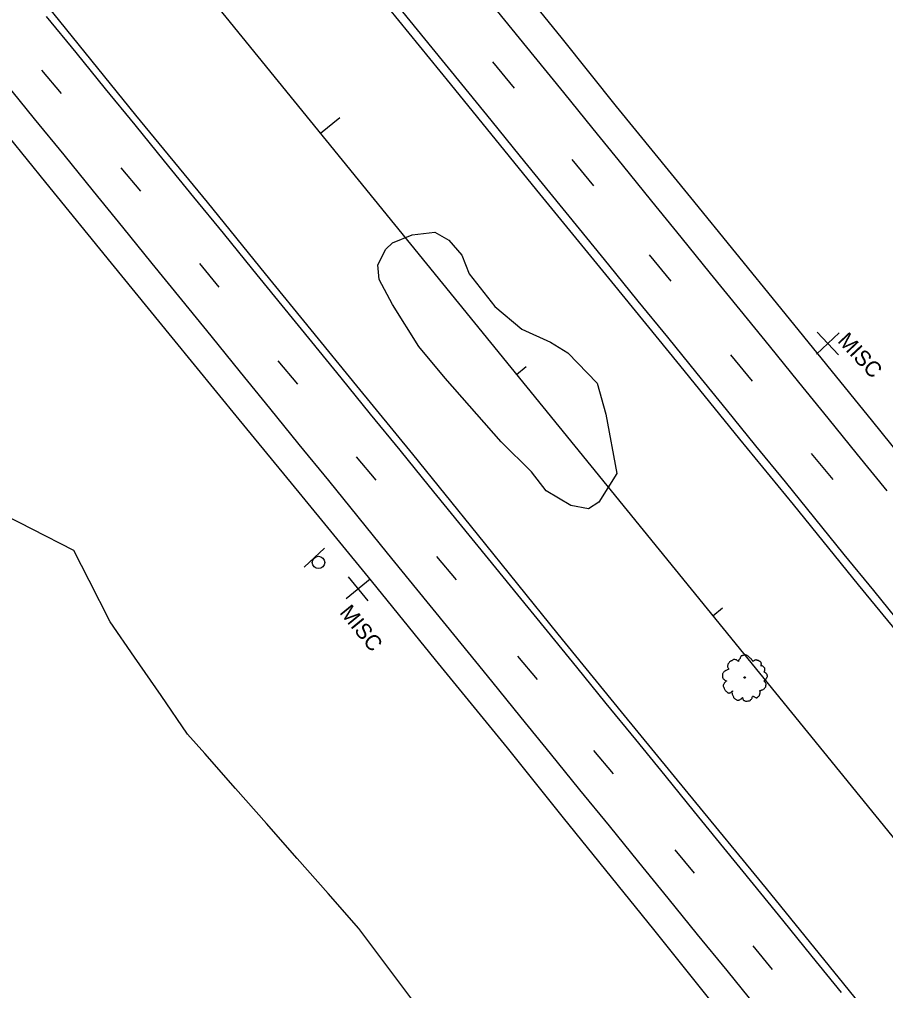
# Model space of a CAD drawing. Extents: x 2132221 to 2141942, y 535736 to 547298.
# Drawn here: x 2137299.4 to 2137577.9, y 541243.7 to 541556.1 of the extents above; entities that cross this region are included whole.
import ezdxf

# ---------------------------------------------------------------- set-up
doc = ezdxf.new("R2010")
doc.units = 0
for name, color, linetype in [('RD_EX_BldgApp', 7, 'Continuous'), ('RD_EX_Misc', 7, 'Continuous'), ('RD_EX_Misc_txCode', 7, 'Continuous'), ('RD_EX_Road', 7, 'Continuous'), ('RD_EX_VEG', 7, 'Continuous'), ('RD_HC_Cl', 7, 'Continuous'), ('RD_HC_Data_Tic', 7, 'Continuous')]:
    doc.layers.add(name, color=color, linetype=linetype)

msp = doc.modelspace()

# ---------------------------------------------------------------- linework, layer by layer
at = {"layer": 'RD_EX_BldgApp'}
msp.add_line((2137397.51, 541385.93), (2137390.9, 541379.82), dxfattribs=at)
msp.add_circle((2137395.56, 541381.38), 2, dxfattribs=at)
at = {"layer": 'RD_EX_Misc'}
for p, q in [((2137451.48, 541542.38), (2137458.5, 541533.93)), ((2137306.47, 541539.77), (2137312.77, 541532.25)), ((2137477.02, 541510.96), (2137484.04, 541502.51)), ((2137332.02, 541508.36), (2137338.32, 541500.83)), ((2137501.88, 541480.29), (2137508.9, 541471.85)), ((2137357.23, 541477.51), (2137363.52, 541469.98)), ((2137555.71, 541448.41), (2137563.01, 541455.25)), ((2137555.94, 541455.47), (2137562.78, 541448.18)), ((2137528.02, 541448.14), (2137535.04, 541439.69)), ((2137382.5, 541446.22), (2137388.79, 541438.69)), ((2137407.71, 541415.37), (2137414, 541407.85)), ((2137553.96, 541416.47), (2137560.98, 541408.02)), ((2137433.54, 541383.33), (2137439.83, 541375.8)), ((2137404.43, 541369.74), (2137412.17, 541376.07)), ((2137405.14, 541376.78), (2137411.46, 541369.03)), ((2137459.53, 541351.27), (2137465.83, 541343.74)), ((2137484.03, 541320.91), (2137490.32, 541313.38)), ((2137510.11, 541288.98), (2137516.4, 541281.46)), ((2137535.21, 541258.02), (2137541.51, 541250.49))]:
    msp.add_line(p, q, dxfattribs=at)
for points in [[(2137445.93, 541567.48), (2137455.38, 541555.83), (2137464.84, 541544.19), (2137474.3, 541532.54), (2137483.75, 541520.9), (2137493.21, 541509.25), (2137502.66, 541497.61), (2137512.12, 541485.97), (2137521.57, 541474.32), (2137531.03, 541462.68), (2137540.48, 541451.03), (2137549.94, 541439.39), (2137559.39, 541427.74), (2137568.85, 541416.1), (2137578.31, 541404.45)], [(2137422.57, 541558.54), (2137432.03, 541546.9), (2137441.5, 541535.26), (2137450.96, 541523.63), (2137460.43, 541511.99), (2137469.89, 541500.35), (2137479.36, 541488.72), (2137488.82, 541477.08), (2137498.29, 541465.44), (2137507.75, 541453.8), (2137517.21, 541442.17), (2137526.68, 541430.53), (2137536.14, 541418.89), (2137545.61, 541407.26), (2137555.07, 541395.62), (2137564.54, 541383.98), (2137574, 541372.35), (2137583.47, 541360.71)], [(2137308.01, 541557.03), (2137317.48, 541545.4), (2137326.95, 541533.77), (2137336.43, 541522.14), (2137345.9, 541510.51), (2137355.37, 541498.88), (2137364.85, 541487.25), (2137374.32, 541475.62), (2137383.79, 541463.99), (2137393.27, 541452.36), (2137402.74, 541440.73), (2137412.21, 541429.1), (2137421.69, 541417.47), (2137431.16, 541405.84), (2137440.63, 541394.21), (2137450.11, 541382.58), (2137459.58, 541370.95), (2137469.05, 541359.32), (2137478.53, 541347.69), (2137488, 541336.06), (2137497.47, 541324.43), (2137506.91, 541312.84), (2137516.37, 541301.2), (2137525.84, 541289.56), (2137535.3, 541277.93), (2137544.77, 541266.29), (2137554.23, 541254.65), (2137563.7, 541243.01)], [(2137294.69, 541535.76), (2137304.15, 541524.12), (2137313.6, 541512.47), (2137323.06, 541500.83), (2137332.52, 541489.19), (2137341.98, 541477.55), (2137351.44, 541465.91), (2137360.9, 541454.26), (2137370.36, 541442.62), (2137379.82, 541430.98), (2137389.27, 541419.34), (2137398.73, 541407.7), (2137408.19, 541396.05), (2137417.65, 541384.41), (2137427.11, 541372.77), (2137436.57, 541361.13), (2137446.03, 541349.49), (2137451.14, 541343.19), (2137460.61, 541331.55), (2137470.07, 541319.91), (2137479.54, 541308.28), (2137489, 541296.64), (2137498.46, 541285), (2137507.93, 541273.36), (2137517.39, 541261.73), (2137526.86, 541250.09), (2137536.32, 541238.45)]]:
    msp.add_lwpolyline(points, dxfattribs=at)
at = {"layer": 'RD_EX_Road'}
for points in [[(2137193.35, 541837.19), (2137212.91, 541812.44), (2137235.27, 541784.87), (2137254.4, 541760.88), (2137274.02, 541736.87), (2137295.29, 541710.97), (2137313.63, 541688.15), (2137334.61, 541662.71), (2137358.33, 541633.36), (2137376.02, 541611.54), (2137393.61, 541589.72), (2137411.3, 541568), (2137437.87, 541535.36), (2137465.67, 541501.18), (2137489.75, 541471.68), (2137511.61, 541444.85), (2137530.92, 541421.07), (2137548.19, 541400.06), (2137569.12, 541374.18), (2137589.5, 541349.39), (2137612.36, 541321.32), (2137632.5, 541296.04), (2137648.27, 541276.75), (2137665.39, 541255.65)], [(2137129.75, 541780.57), (2137152.42, 541752.13), (2137176.05, 541723.37), (2137199.18, 541694.95), (2137221.19, 541667.61), (2137243.48, 541640.3), (2137267.28, 541610.96), (2137291.46, 541581.15), (2137312.24, 541555.53), (2137336.72, 541525.3), (2137359.73, 541497.32), (2137378.4, 541474.19), (2137407.74, 541438.19), (2137425.75, 541416.17), (2137446.57, 541390.46), (2137472.54, 541358.27), (2137492.89, 541333.37), (2137514.29, 541307.17), (2137539.52, 541276.53), (2137564.39, 541245.78), (2137586.4, 541218.72), (2137608.31, 541191.93)], [(2137100.38, 541758.24), (2137116.65, 541738.05), (2137136.57, 541713.17), (2137158.12, 541686.61), (2137181.43, 541658.3), (2137199.12, 541636.62), (2137219.56, 541611.48), (2137227.67, 541601.79), (2137247.01, 541578.63), (2137263.16, 541558.53), (2137284.05, 541532.79), (2137307.73, 541503.58), (2137328.85, 541477.64), (2137348.35, 541453.76), (2137369.96, 541427.39), (2137389.21, 541403.83), (2137412.54, 541375.44), (2137433.11, 541350), (2137456.28, 541321.75), (2137474.25, 541299.22), (2137503.28, 541263.26), (2137525.6, 541235.47)], [(2137457.68, 541569.82), (2137473.88, 541549.77), (2137491.32, 541528.01), (2137515.2, 541498.79), (2137544.12, 541463.2), (2137573.71, 541426.73), (2137595.07, 541400.23), (2137611.36, 541380.03), (2137614.73, 541374.83), (2137617.63, 541368.59), (2137619.19, 541368), (2137623.18, 541367.48), (2137626.31, 541363.68), (2137627.71, 541361.27), (2137643.36, 541341.41), (2137658.35, 541323.01), (2137679.14, 541297.23), (2137696.06, 541276.5)]]:
    msp.add_lwpolyline(points, dxfattribs=at)
at = {"layer": 'RD_EX_VEG'}
msp.add_lwpolyline([(2137454.29, 541420.16), (2137436.27, 541440.67), (2137427.84, 541450.8), (2137419.36, 541464.4), (2137415.07, 541472.45), (2137414.68, 541477.07), (2137417.19, 541482.16), (2137419.38, 541484.19), (2137425.73, 541486.72), (2137432.97, 541487.67), (2137437.47, 541485), (2137441.7, 541480.22), (2137443.96, 541474.17), (2137452.28, 541463.75), (2137460.92, 541456.39), (2137470.14, 541452.2), (2137475.7, 541448.78), (2137485.21, 541439.08), (2137487.97, 541429.08), (2137491.53, 541410.01), (2137485.68, 541400.74), (2137482.43, 541398.66), (2137476.71, 541399.65), (2137468.77, 541404.45), (2137464.11, 541410.49)], close=True, dxfattribs=at)
msp.add_lwpolyline([(2137428.45, 541237.07), (2137419.45, 541249.07), (2137410.45, 541261.08), (2137408.55, 541263.61), (2137398.64, 541274.86), (2137388.72, 541286.12), (2137378.81, 541297.38), (2137368.89, 541308.63), (2137358.98, 541319.89), (2137353.42, 541326.19), (2137344.92, 541338.55), (2137336.41, 541350.9), (2137328.58, 541362.27), (2137321.75, 541375.62), (2137316.83, 541385.25), (2137303.46, 541392.04), (2137299.47, 541394.07), (2137293.84, 541396.93)], dxfattribs=at)
for centre, radius in [((2137532.59, 541344.38), 0.25), ((2137532.57, 541344.38), 0.0001)]:
    msp.add_circle(centre, radius, dxfattribs=at)
for points in [[(2137537.95, 541349.15), (2137537.76, 541349.38), (2137537.47, 541349.56), (2137537.23, 541349.67), (2137537.02, 541349.79), (2137536.79, 541349.88), (2137536.46, 541349.98), (2137536.16, 541350.01), (2137535.89, 541349.94), (2137535.69, 541349.82), (2137535.46, 541349.67), (2137535.33, 541349.55), (2137535.23, 541349.63), (2137535.14, 541349.75), (2137535.03, 541349.99), (2137534.86, 541350.17), (2137534.69, 541350.36), (2137534.43, 541350.6), (2137534.2, 541350.85), (2137533.97, 541351.02), (2137533.72, 541351.23), (2137533.37, 541351.42), (2137533.04, 541351.59), (2137532.65, 541351.64), (2137532.14, 541351.5), (2137531.79, 541351.36), (2137531.51, 541351.3), (2137531.28, 541350.88), (2137531.14, 541350.52), (2137531.01, 541350.36), (2137530.75, 541350.02), (2137530.65, 541349.79), (2137530.59, 541349.57), (2137530.52, 541349.6), (2137530.23, 541349.85), (2137529.95, 541350), (2137529.5, 541350.16), (2137529.18, 541350.17), (2137528.88, 541350.02), (2137528.6, 541349.8), (2137528.39, 541349.74), (2137528.13, 541349.61), (2137528.06, 541349.58), (2137527.79, 541349.4), (2137527.53, 541349.02), (2137527.29, 541348.76), (2137527.21, 541348.52), (2137527.18, 541348.29), (2137527.11, 541347.99), (2137527.22, 541347.54), (2137527.37, 541347.24), (2137527.48, 541347.07), (2137527, 541346.86), (2137526.71, 541346.66), (2137526.33, 541346.48), (2137526.27, 541346.43), (2137525.89, 541346.15), (2137525.75, 541345.82), (2137525.53, 541345.51), (2137525.48, 541345.23), (2137525.45, 541344.82), (2137525.5, 541344.43), (2137525.75, 541343.98), (2137526.04, 541343.7), (2137526.56, 541343.4), (2137526.78, 541343.26), (2137526.64, 541343.16), (2137526.38, 541342.89), (2137526.07, 541342.6), (2137525.93, 541342.27), (2137525.79, 541342.01), (2137525.71, 541341.73), (2137525.77, 541341.34), (2137525.98, 541341), (2137526.16, 541340.58), (2137526.41, 541340.2), (2137526.73, 541339.82), (2137527.25, 541339.48), (2137527.53, 541339.36), (2137527.72, 541339.41), (2137528.14, 541339.51), (2137528.27, 541339.7), (2137528.72, 541340.09), (2137528.66, 541339.9), (2137528.52, 541339.53), (2137528.64, 541338.96), (2137528.79, 541338.55), (2137529, 541338.1), (2137529.15, 541337.83), (2137529.52, 541337.53), (2137529.83, 541337.31), (2137530.18, 541337.12), (2137530.58, 541337.08), (2137530.9, 541337.14), (2137531.14, 541337.29), (2137531.47, 541337.49), (2137531.63, 541337.57)], [(2137531.63, 541337.57), (2137531.71, 541337.74), (2137531.86, 541337.95), (2137531.89, 541337.88), (2137531.97, 541337.72), (2137532.07, 541337.43), (2137532.16, 541337.21), (2137532.4, 541336.99), (2137532.66, 541336.86), (2137533.17, 541336.71), (2137533.7, 541336.83), (2137534.18, 541336.9), (2137534.47, 541337.07), (2137534.61, 541337.26), (2137534.96, 541337.61), (2137535, 541337.93), (2137535.06, 541338.05), (2137535.29, 541338.4), (2137535.38, 541338.37), (2137535.6, 541338.21), (2137535.94, 541338.02), (2137536.22, 541337.9), (2137536.5, 541337.85), (2137536.72, 541337.95), (2137537, 541338.24), (2137537.32, 541338.47), (2137537.38, 541338.63), (2137537.43, 541338.8), (2137537.52, 541339), (2137537.53, 541339.21), (2137537.57, 541339.38), (2137537.58, 541339.52), (2137537.6, 541339.72), (2137537.58, 541339.93), (2137537.51, 541340.07), (2137537.59, 541340.21), (2137537.84, 541340.24), (2137537.94, 541340.27), (2137538.13, 541340.4), (2137538.54, 541340.48), (2137538.86, 541340.71), (2137539.14, 541341.03), (2137539.31, 541341.26), (2137539.41, 541341.55), (2137539.46, 541341.87), (2137539.5, 541342.08), (2137539.48, 541342.29), (2137539.35, 541342.62), (2137539.21, 541342.84), (2137538.98, 541343.09), (2137538.88, 541343.27), (2137538.93, 541343.29), (2137539.04, 541343.39), (2137539.24, 541343.58), (2137539.52, 541343.94), (2137539.79, 541344.39), (2137539.81, 541344.4), (2137539.92, 541344.65), (2137539.92, 541344.95), (2137539.87, 541345.14), (2137539.83, 541345.38), (2137539.68, 541345.58), (2137539.48, 541345.8), (2137539.25, 541345.96), (2137539.04, 541346.04), (2137538.83, 541346.09), (2137538.89, 541346.24), (2137539.04, 541346.52), (2137539.12, 541346.66), (2137539.15, 541346.89), (2137539.14, 541347.19), (2137538.93, 541347.6), (2137538.45, 541348.01), (2137538.1, 541348.1), (2137537.87, 541348.09), (2137537.93, 541348.21), (2137537.94, 541348.49), (2137538, 541348.68), (2137537.97, 541348.9), (2137537.94, 541349.08), (2137537.91, 541349.18)]]:
    msp.add_spline(points, degree=3, dxfattribs=at)
at = {"layer": 'RD_HC_Cl'}
msp.add_line((2136971.61, 542041.65), (2141699.63, 536226.46), dxfattribs=at)
at = {"layer": 'RD_HC_Data_Tic'}
for p, q in [((2137396.19, 541519.44), (2137402.4, 541524.48)), ((2137459.28, 541441.85), (2137462.38, 541444.37)), ((2137522.36, 541364.26), (2137525.47, 541366.78))]:
    msp.add_line(p, q, dxfattribs=at)

# ---------------------------------------------------------------- texts
at = {"layer": 'RD_EX_Misc_txCode'}
for rotation, p in [(313.1485, (2137560.97, 541453.81)), (309.2571, (2137400.92, 541366.63))]:
    msp.add_text(' MISC', height=5, rotation=rotation, dxfattribs=at).set_placement(p)

doc.saveas('drawing.dxf')
